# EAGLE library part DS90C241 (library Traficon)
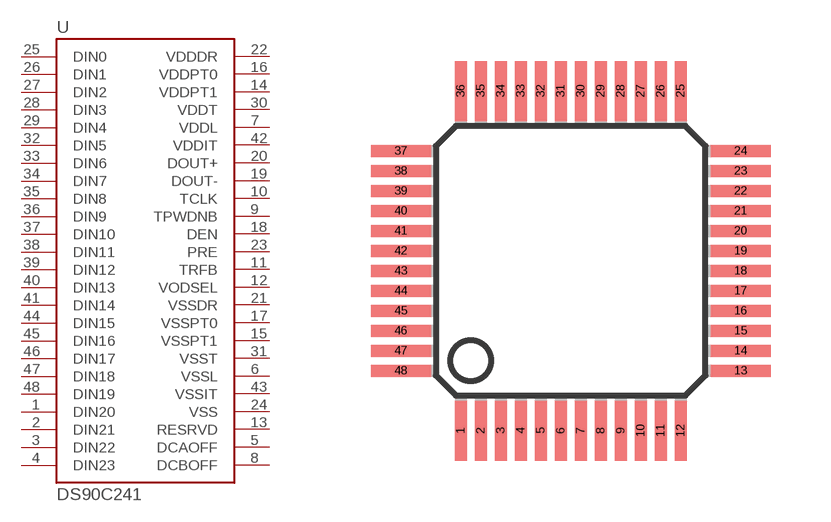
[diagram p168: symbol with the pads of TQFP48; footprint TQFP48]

Designator prefix U

## DS90C241  [TQFP48]
1  DIN20  in
2  DIN21  in
3  DIN22  in
4  DIN23  in
5  DCAOFF  pas
6  VSSL  sup
7  VDDL  sup
8  DCBOFF  pas
9  TPWDNB  in
10  TCLK  in
11  TRFB  in
12  VODSEL  in
13  RESRVD  pas
14  VDDPT1  sup
15  VSSPT1  sup
16  VDDPT0  sup
17  VSSPT0  sup
18  DEN  in
19  DOUT-  out
20  DOUT+  out
21  VSSDR  sup
22  VDDDR  sup
23  PRE  in
24  VSS  sup
25  DIN0  in
26  DIN1  in
27  DIN2  in
28  DIN3  in
29  DIN4  in
30  VDDT  sup
31  VSST  sup
32  DIN5  in
33  DIN6  in
34  DIN7  in
35  DIN8  in
36  DIN9  in
37  DIN10  in
38  DIN11  in
39  DIN12  in
40  DIN13  in
41  DIN14  in
42  VDDIT  sup
43  VSSIT  sup
44  DIN15  in
45  DIN16  in
46  DIN17  in
47  DIN18  in
48  DIN19  in

## Footprint TQFP48 (pad centres in mm)
Thin Quad Flat Pack
smd 0.3 x 1.5: 1 -2.75,-4.25; 2 -2.25,-4.25; 3 -1.75,-4.25; 4 -1.25,-4.25; 5 -0.75,-4.25; 6 -0.25,-4.25; 7 0.25,-4.25; 8 0.75,-4.25; 9 1.25,-4.25; 10 1.75,-4.25; 11 2.25,-4.25; 12 2.75,-4.25; 25 2.75,4.25; 26 2.25,4.25; 27 1.75,4.25; 28 1.25,4.25; 29 0.75,4.25; 30 0.25,4.25; 31 -0.25,4.25; 32 -0.75,4.25; 33 -1.25,4.25; 34 -1.75,4.25; 35 -2.25,4.25; 36 -2.75,4.25
smd 1.5 x 0.3: 13 4.25,-2.75; 14 4.25,-2.25; 15 4.25,-1.75; 16 4.25,-1.25; 17 4.25,-0.75; 18 4.25,-0.25; 19 4.25,0.25; 20 4.25,0.75; 21 4.25,1.25; 22 4.25,1.75; 23 4.25,2.25; 24 4.25,2.75; 37 -4.25,2.75; 38 -4.25,2.25; 39 -4.25,1.75; 40 -4.25,1.25; 41 -4.25,0.75; 42 -4.25,0.25; 43 -4.25,-0.25; 44 -4.25,-0.75; 45 -4.25,-1.25; 46 -4.25,-1.75; 47 -4.25,-2.25; 48 -4.25,-2.75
